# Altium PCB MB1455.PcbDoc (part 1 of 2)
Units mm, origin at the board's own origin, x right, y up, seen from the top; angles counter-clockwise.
Board outline 18.54 x 50.29 mm, 4 copper layers (Top Layer, Inner 1, Inner 2, Bottom Layer), stack 1.577 mm thick; 92 components, 84 nets, 350 pads, 195 vias.
Unrouted connection lines stored in the file: 7.
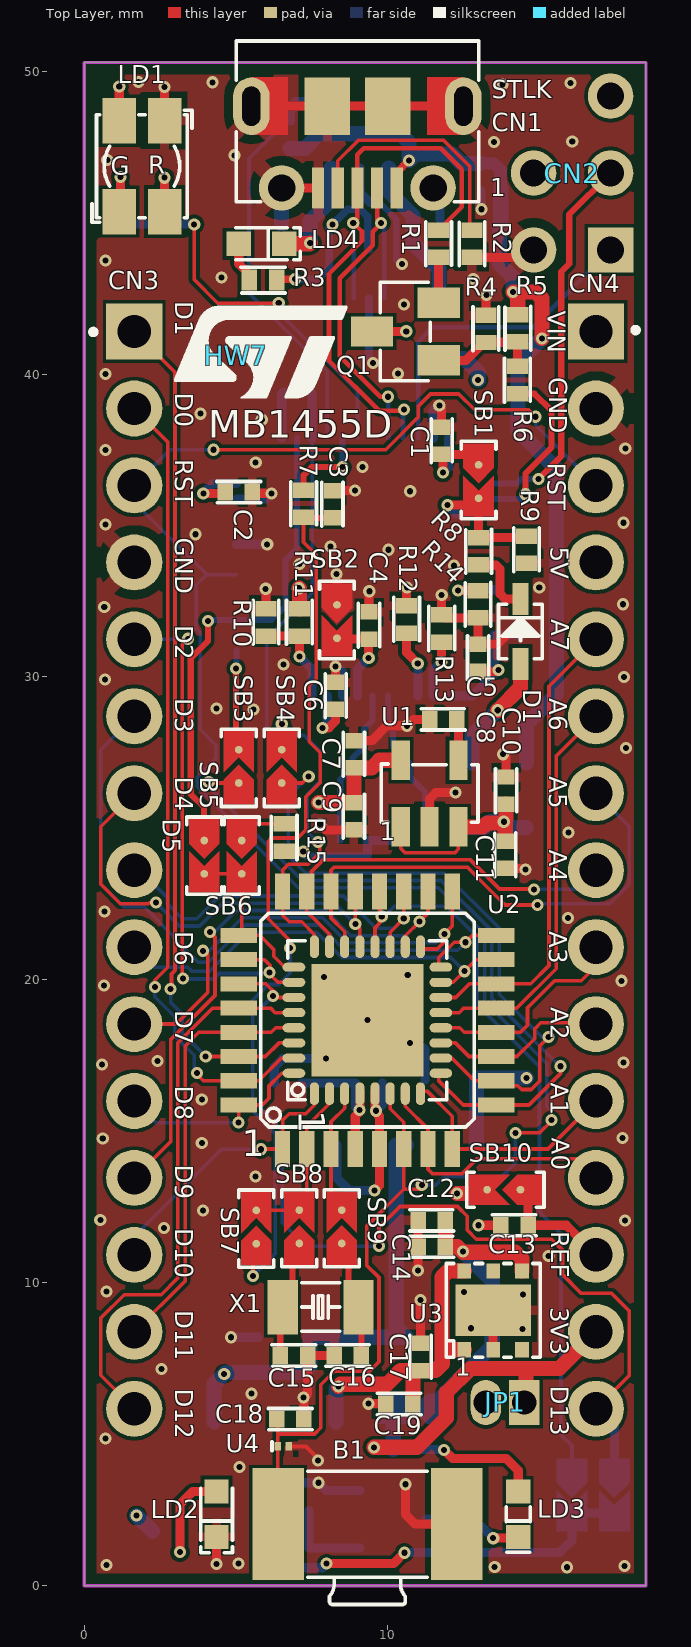
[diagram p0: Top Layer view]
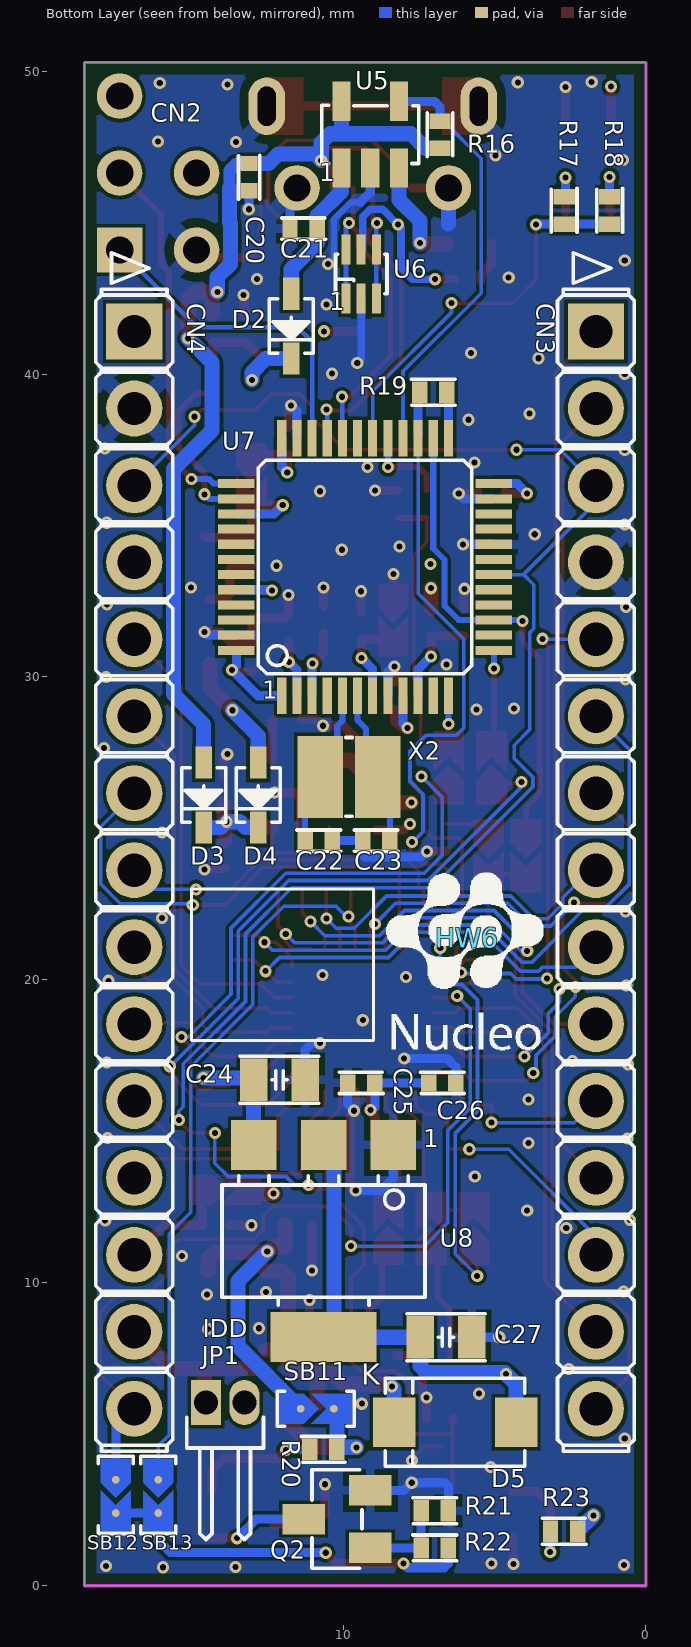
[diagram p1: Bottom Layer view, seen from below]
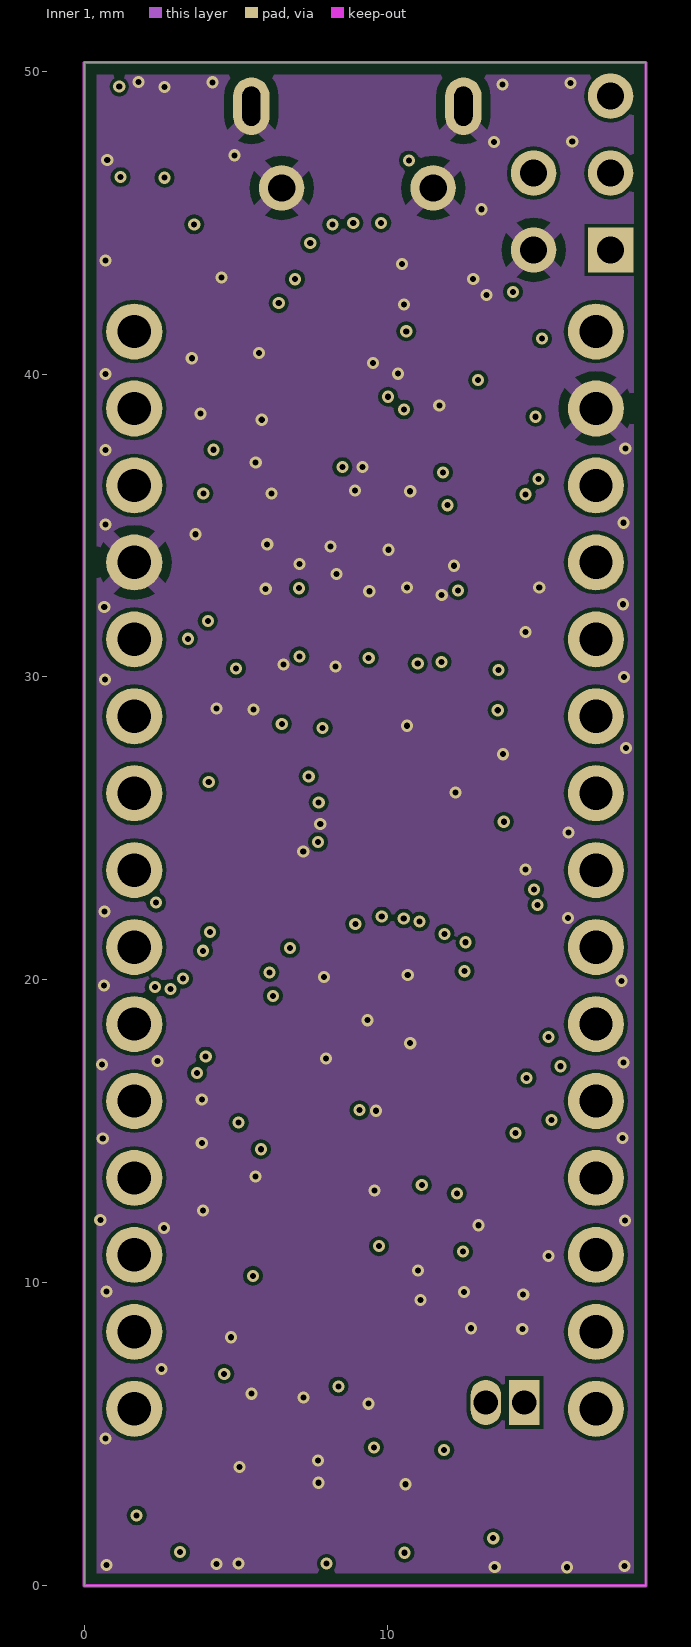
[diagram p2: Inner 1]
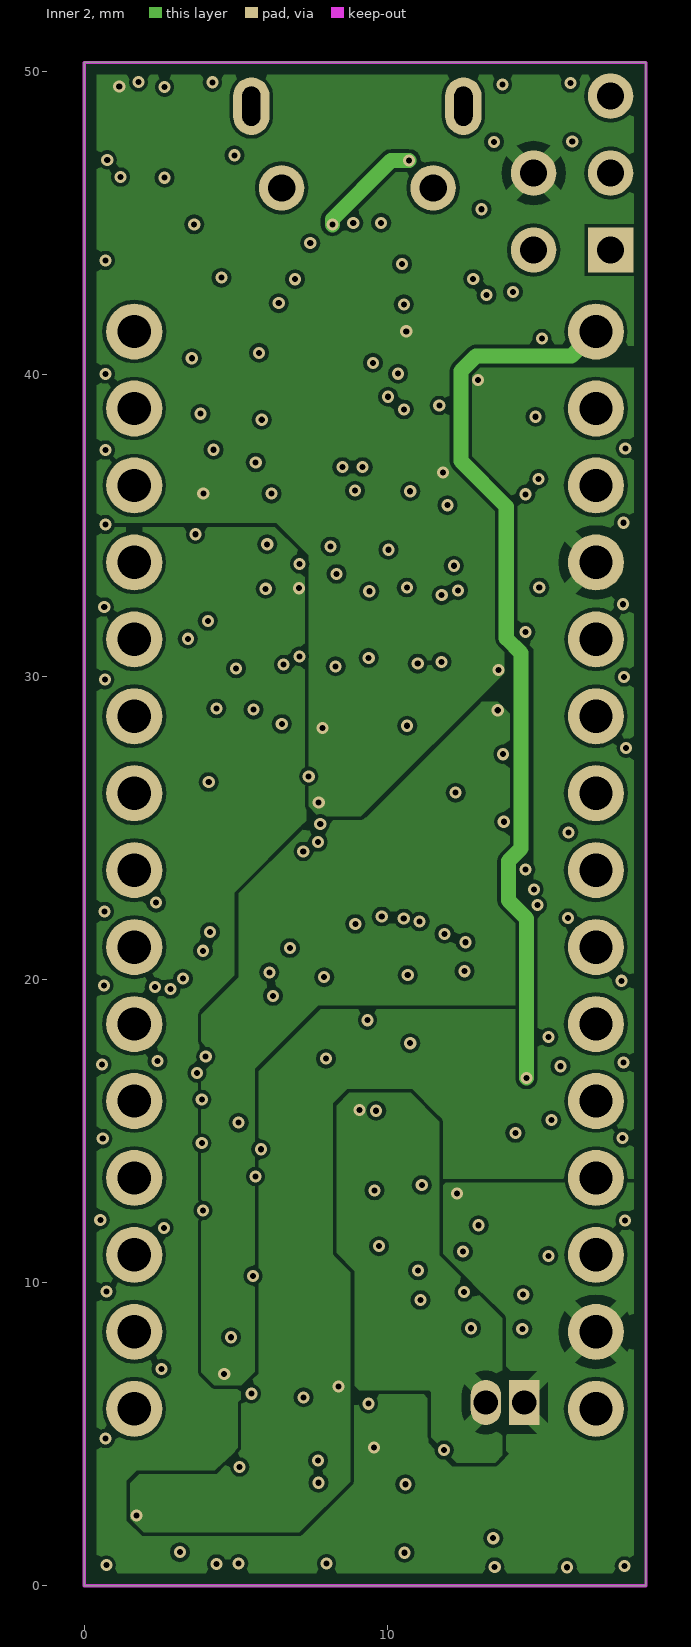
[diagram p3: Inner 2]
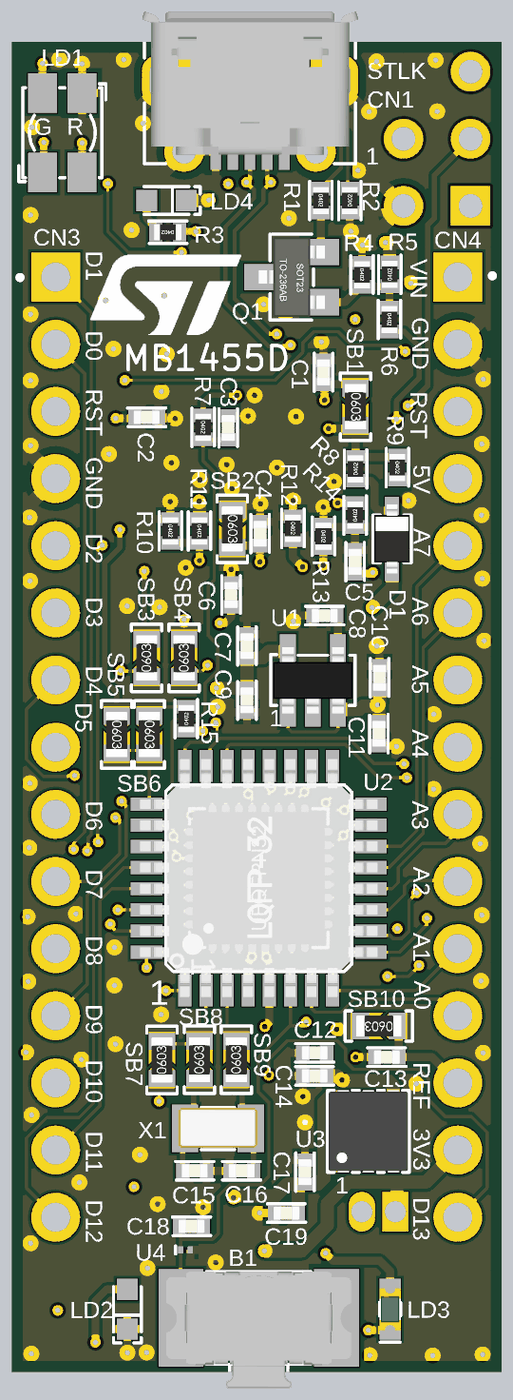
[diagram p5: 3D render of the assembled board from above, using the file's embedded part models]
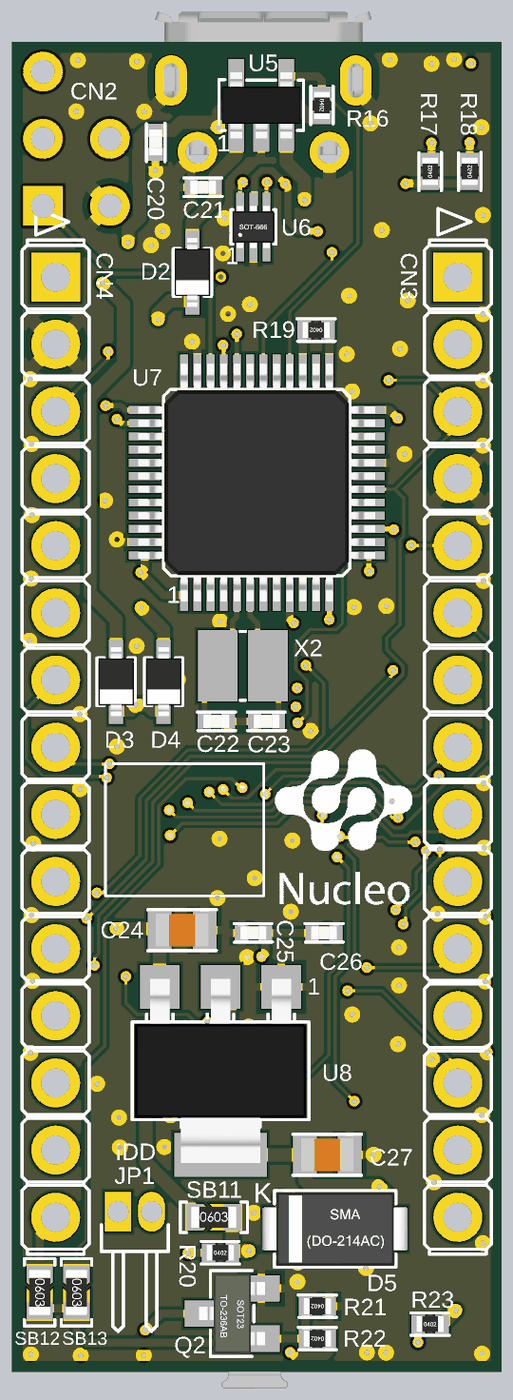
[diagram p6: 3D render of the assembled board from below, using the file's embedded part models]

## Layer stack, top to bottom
Top Solder: solder mask 0.015, Solder Resist, Dk 3.5
Top Layer: signal copper 0.035
Dielectric 1: core 0.254, FR-4, Dk 4.2
Inner 1: signal copper 0.036
Dielectric 3: prepreg 0.927, Dk 4.2
Inner 2: signal copper 0.036
Dielectric 2: core 0.254, Dk 4.2
Bottom Layer: signal copper 0.035
Bottom Solder: solder mask 0.015, Solder Resist, Dk 3.5

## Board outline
0,0 18.542,0 18.542,50.292 0,50.292

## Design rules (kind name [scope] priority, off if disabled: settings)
BoardOutlineClearance [OnLayer('Top Layer') or OnLayer('Bottom Layer') or OnLayer('Inner 1') or OnLayer('Inner 2')] p1: gap=0.4 ignorepadtopadclearanceinfootprint=FALSE
Clearance [All] p1: gap=0.12 ignorepadtopadclearanceinfootprint=FALSE
ComponentClearance [All] p1: gap=0.2 collisioncheckmode=3 verticalgap=0.2 showdistances=FALSE
DiffPairsRouting [All] p1: maxlimit=0.254 minlimit=0.2 mostfreqgap=0.254 toplayer_minwidth=0.152 toplayer_maxwidth=0.381 toplayer_prefwidth=0.381 midlayer1_minwidth=0.152 midlayer1_maxwidth=0.381 midlayer1_prefwidth=0.381 midlayer2_minwidth=0.152 midlayer2_maxwidth=0.381 midlayer2_prefwidth=0.381 bottomlayer_minwidth=0.152 bottomlayer_maxwidth=0.381 bottomlayer_prefwidth=0.381 maxuncoupledlength=25
HoleSize [All] p1: absolutevalues=TRUE maxlimit=10 minlimit=0.025 maxpercent=80.000 minpercent=20.000
MinimumSolderMaskSliver [All] p1: minsoldermaskwidth=0.1
PlaneConnect [All] p1: planeconnectstyle=Relief reliefexpansion=0.508 reliefentries=4 reliefconductorwidth=0.21 reliefairgap=0.21
PolygonConnect [All] p1: thpad.connectstyle=Relief thpad.reliefconductorwidth=0.5 thpad.reliefentries=4 thpad.polygonreliefangle="45 Angle" thpad.airgapwidth=0.3 smdpad.connectstyle=Relief smdpad.reliefconductorwidth=0.3 smdpad.reliefentries=4 smdpad.polygonreliefangle="90 Angle" smdpad.airgapwidth=0.2 via.connectstyle=Direct via.reliefconductorwidth=0.2 via.reliefentries=4 via.polygonreliefangle="90 Angle" via.airgapwidth=0.2
RoutingVias [All] p1: holewidth=0.3 width=0.8 viastyle="Through Hole" minholewidth=0.2 minwidth=0.4 maxholewidth=0.3 maxwidth=1.5
SilkToSilkClearance [All] p1: silktosilkclearance=0.1
SilkToSolderMaskClearance [IsPad] p1: minsilkscreentomaskgap=0.2 clearancetoexposedcopper=TRUE
SolderMaskExpansion SolderMaskExpansion_via [IsVia] p1: expansion=0.05 istentingtop=FALSE soldermaskfromhole=TRUE
SolderMaskExpansion [All] p2: expansion=0.102 istentingtop=FALSE
Width [All] p1: maxlimit=1 minlimit=0.12 preferedwidth=0.254 toplayer_prefwidth=0.2 midlayer1_maxwidth=0.512 midlayer2_maxwidth=0.512 bottomlayer_prefwidth=0.2 minimp=50.000000 maximp=50.000000 favimp=50.000000
23 further rules are at their usual default settings.

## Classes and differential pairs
component class Mechanical: HW3 HW6 HW7
component class U_Power: C7 C8 C9 C10 C11 C12 C14 C17 C19 C24 C27 D2 D3 D4 D5 JP1 LD2 R23 SB11 U1 U3 U8
component class U_ST_LINK_V2-1: C1 C2 C3 C4 C5 C6 C20 C21 C22 C23 CN1 CN2 D1 LD1 LD4 Q1 R1 R2 R3 R4 R5 R6 R7 R8 R9 R10 R11 R12 R13 R14 R16 R17 R18 R19 SB1 SB2 SB3 SB4 U5 U6 U7 X2
component class U_STM32G0_microcontroller: B1 C13 C15 C16 C18 C25 C26 CN3 CN4 LD3 Q2 R15 R20 R21 R22 SB5 SB6 SB7 SB8 SB9 SB10 SB12 SB13 U2 U4 X1
differential pair STLK_USB_D: +STLK_USB_D_P -STLK_USB_D_N

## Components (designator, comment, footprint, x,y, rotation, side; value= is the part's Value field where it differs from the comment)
B1 "SW-PB" SWI_C&K_ITT_KSS221G 9.347,2.032 r0 top locked value=KSS221GLFS
C1 "Capacitor" C0402 11.8,37.8 r270 top value=100nF
C2 "Capacitor" C0402 5.1,36.1 r180 top value=100nF
C3 "Capacitor" C0402 8.19,35.7 r270 top value=20pF
C4 "Capacitor" C0402 9.4,31.7 r270 top value=100nF
C5 "Capacitor" C0402 13,30.634 r270 top value=100nF
C6 "Capacitor" C0402 8.3,29.38 r270 top value=100nF
C7 "Capacitor" C0402 8.9,27.45 r270 top value=100nF
C8 "Capacitor" C0402 11.85,28.6 r0 top value=10nF
C9 "Capacitor" C0402 8.9,25.4 r90 top value=1uF
C10 "Capacitor" C0402 13.926,26.248 r270 top value=1uF
C11 "Capacitor" C0402 13.9,24.132 r90 top value=100nF
C12 "Capacitor" C0402 11.47,12.06 r0 top value=1uF
C13 "Capacitor" C0402 14.2,11.9 r0 top value=100nF
C14 "Capacitor" C0402 11.47,11.19 r0 top value=100nF
C15 "Capacitor" C0402 6.921,7.6 r180 top value=5.6pF
C16 "Capacitor" C0402 8.7,7.6 r0 top value=5.6pF
C17 "Capacitor" C0402 11.1,7.55 r270 top value=100nF
C18 "Capacitor" C0402 6.8,5.5 r180 top value=100nF
C19 "Capacitor" C0402 10.4,6 r0 top value=1uF
C20 "Capacitor" C0402 13.1,46.5 r90 bottom value=1uF
C21 "Capacitor" C0402 11.3,44.8 r180 bottom value=100nF
C22 "Capacitor" C0402 10.8,24.6 r0 bottom value=10pF
C23 "Capacitor" C0402 8.9,24.6 r180 bottom value=10pF
C24 "Capacitor" C0805 12.1,16.7 r0 bottom value=10uF
C25 "Capacitor" C0402 9.4,16.6 r180 bottom value=100nF
C26 "Capacitor" C0402 6.722,16.6 r0 bottom value=4.7uF
C27 "Capacitor" C0805 6.6,8.204 r0 bottom value=10uF
CN1 "USB_uB_105017.0001" CON_USBMICROB_MOLEX_105017-0001_H2P90 9.017,50.292 r180 top locked value=USB_uB_105017-0001
CN2 "Header STLINK" HDR_1x5_2R54_V_M 17.374,44.094 r90 top locked value=N/A
CN3 "Header 15x1" CON_LYCN_313115S161145 1.651,23.622 r270 bottom locked value="Header 15X1"
CN4 "Header 15x1" CON_LYCN_313115S161145 16.891,23.622 r270 bottom locked value="Header 15X1"
D1 "BAT60JFILM" DIO_SOD323 14.4,31.5 r90 top
D2 "BAT60JFILM" DIO_SOD323 11.71,41.58 r270 bottom
D3 "BAT60JFILM" DIO_SOD323 14.6,26.1 r270 bottom
D4 "BAT60JFILM" DIO_SOD323 12.8,26.1 r270 bottom
D5 "STPS1L40M" DIO_SMA_1A_2K 6.3,5.4 r180 bottom locked value=STPS1L30A
HW6 "Logo" LOGO_NUCLEO 5.9,21.39 r180 bottom value="LOGO NUCLEO"
HW7 "Logo" ST_LOGO_5mm 5,40.6 r0 top value=N/A
JP1 "Jumper_Header1.27 2x1 Fitted" CON_WP_707-2-02-2-20-00 13.89,6.05 r180 top value="Header 2x1"
LD1 "LD_BICOLOR_CMS" LED_BI-GR_HSMF-A201-A00J1 1.905,46.863 r180 top locked value=Red/Yellow-Green
LD2 "LED_red" LED_0603_VISHAY_VLMS1300-GS08_RED_1A2K_H0P8 4.369,2.362 r270 top locked value=Red
LD3 "LED_green" LED_0603_GREEN 14.326,2.362 r270 top locked value=Green
LD4 "LED_red" LED_0603_VISHAY_VLMS1300-GS08_RED_1A2K_H0P8 5.85,44.3 r0 top value=Red
Q1 "9013-SOT23" NPN_SOT23 10.6,41.402 r90 top value=BSR14
Q2 "9013-SOT23" NPN_SOT23 10.2,2.2 r90 bottom value=BSR14
R1 "Resistor" R0402 11.7,44.3 r270 top value=1K5
R2 "Resistor" R0402 12.8,44.3 r90 top value=100K
R3 "Resistor" R0402 5.9,43.1 r180 top value=1K
R4 "Resistor" R0402 13.26,41.49 r270 top value=36K
R5 "Resistor" R0402 14.313,41.51 r90 top value=10K
R6 "Resistor" R0402 14.3,39.8 r270 top value=100R
R7 "Resistor" R0402 7.24,35.72 r270 top value=100R
R8 "Resistor" R0402 13.017,34.15 r90 top value=2K7
R9 "Resistor" R0402 14.6,34.2 r270 top value=4K7
R10 "Resistor" R0402 6,31.8 r270 top value=4K7
R11 "Resistor" R0402 7.1,31.8 r270 top value=4K7
R12 "Resistor" R0402 10.643,31.9 r270 top value=10K
R13 "Resistor" R0402 11.8,31.6 r270 top value=10K
R14 "Resistor" R0402 13,32.4 r90 top value=100K
R15 "Resistor" R0402 6.6,24.7 r90 top value=10K
R16 "Resistor" R0402 6.8,47.9 r270 bottom value=10K
R17 "Resistor" R0402 2.7,45.4 r90 bottom value=560R
R18 "Resistor" R0402 1.2,45.4 r90 bottom value=560R
R19 "Resistor" R0402 7.021,39.4 r0 bottom value=100R
R20 "Resistor" R0402 10.65,4.5 r180 bottom value=510R
R21 "Resistor" R0402 6.971,2.475 r0 bottom value=100K
R22 "Resistor" R0402 6.971,1.25 r0 bottom value=47K
R23 "Resistor" R0402 2.7,1.8 r180 bottom value=1K
SB1 "SB_ON" SOLDER-BRIDGE_R0603-0R 13.017,36.5 r270 top value=0R
SB2 "SB_ON" SOLDER-BRIDGE_R0603-0R 8.343,31.88 r270 top value=0R
SB3 "SB_ON" SOLDER-BRIDGE_R0603-0R 5.1,27 r90 top value=0R
SB4 "SB_ON" SOLDER-BRIDGE_R0603-0R 6.521,27 r90 top value=0R
SB5 "SB_ON" SOLDER-BRIDGE_R0603-0R 3.96,24.1 r270 top value=0R
SB6 "SB_ON" SOLDER-BRIDGE_R0603-0R 5.2,24.1 r270 top value=0R
SB7 "SB_ON" SOLDER-BRIDGE_R0603-0R 5.68,11.79 r90 top value=0R
SB8 "SB_ON" SOLDER-BRIDGE_R0603-0R 7.1,11.8 r90 top value=0R
SB9 "SB_ON" SOLDER-BRIDGE_R0603-0R 8.5,11.8 r90 top value=0R
SB10 "SB_ON" SOLDER-BRIDGE_R0603-0R 13.9,13.075 r180 top value=0R
SB11 "SB_ON" SOLDER-BRIDGE_R0603-0R 10.9,5.842 r180 bottom value=0R
SB12 "SB_ON" SOLDER-BRIDGE_R0603-0R 17.5,3 r270 bottom value=0R
SB13 "SB_ON" SOLDER-BRIDGE_R0603-0R 16.1,3 r270 bottom value=0R
U1 "LDK120M33R" REG_SOT23-5L 11.4,26.15 r0 top
U2 "STM32G031K8T6U" ICC_LQFP32_7X7_P080__UFQFPN32-EPAD_5X5_P050__DI 9.347,18.669 r0 top value=STM32G031K8T6
U3 "LD39050PU33R" ICC_DFN6-EPAD_3X3_P095 13.5,9.09 r0 top
U4 "ESD-TRANSIL" ESD_0201_H0P3_1K_2A_REF2 6.571,4.602 r0 top value=ESDZL5-1F4
U5 "STMPS2141STR" MOS_SOT23-5L 9.1,47.9 r180 bottom
U6 "USBLC6-2P6" ESD_SOT666 9.4,43.3 r180 bottom
U7 "STM32F103CBT6" ICC_LQFP48_7X7_P050 9.271,33.63 r180 bottom locked
U8 "LD1117S50TR" REG_SOT223-TAB 10.643,11.379 r0 bottom
X1 "XTAL_2_PINS" CRY_NX3215SA_2P 7.8,9.2 r0 top value=32.768kHz
X2 "XTAL_2_PINS" CRY_NX3225GD_2P 9.8,26.7 r180 bottom value=8MHz

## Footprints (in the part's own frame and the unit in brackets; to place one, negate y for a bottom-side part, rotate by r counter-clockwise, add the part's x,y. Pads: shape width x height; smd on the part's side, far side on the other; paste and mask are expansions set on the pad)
C0402 [mm]
  rect 0.51x0.56 smd mask+0.05: 1(-0.45,0) 2(0.45,0)
  silkscreen extent -0.72,-0.35 0.72,0.35, body extent -0.5,-0.3 0.5,0.3, height 0.4
C0805 [mm]
  rect 0.9x1.4 smd mask+0.05: 1(-0.85,0) 2(0.85,0)
  silkscreen extent -1.3,-0.77 1.3,0.77, body extent -1.1,-0.7 1.1,0.7, height 1.35
CON_LYCN_313115S161145 [mm]
  rect 1.85x1.85 / inner round 1.85 / far side rect 1.85x1.85 hole 1.1 mask+0.05: 1(-17.78,0)
  round 1.85 hole 1.1 mask+0.05: 2(-15.24,0) 3(-12.7,0) 4(-10.16,0) 5(-7.62,0) 6(-5.08,0) 7(-2.54,0) 8(0,0) 9(2.54,0) 10(5.08,0) 11(7.62,0) 12(10.16,0) 13(12.7,0) 14(15.24,0) 15(17.78,0)
  silkscreen extent -20.38,-1.27 19.18,1.27, body extent -19.18,-1.27 19.18,1.27, height 8.5
CON_USBMICROB_MOLEX_105017-0001_H2P90 [mm]
  rect 0.4x1.35 smd mask+0.05: 1(-1.3,4.15) 2(-0.65,4.15) 3(0,4.15) 4(0.65,4.15) 5(1.3,4.15)
  round 1.5 hole 0.9 mask+0.05: 6(-2.5,4.15) 7(2.5,4.15)
  oval 1.2x1.9 hole 0.6 slot 1.3 at 90 deg mask+0.05: 8(3.5,1.45) 9(-3.5,1.45)
  rect 1.5x1.9 smd mask+0.05: 10(-1,1.45) 11(1,1.45)
  Top Layer region: 2.3,2.4 3.5,2.4 3.5,0.5 2.3,0.5
  Top Layer region: -3.5,2.4 -2.3,2.4 -2.3,0.5 -3.5,0.5
  silkscreen extent -4,-0.7 4,4.6, body extent -4.1,-1.15 4.1,4.66, height 2.9
CON_WP_707-2-02-2-20-00 [mm]
  rect 1x1.5 hole 0.8 mask+0.05: 1(-0.635,0)
  oval 1x1.5 hole 0.8 mask+0.05: 2(0.635,0)
CRY_NX3215SA_2P [mm]
  rect 1x1.8 smd mask+0.05: 1(-1.25,0) 2(1.25,0)
  silkscreen extent -0.63,-0.8 0.63,0.8, body extent -1.65,-0.8 1.65,0.8, height 0.9
CRY_NX3225GD_2P [mm]
  rect 1.5x2.7 smd mask+0.05: 1(-0.95,0) 2(0.95,0)
  silkscreen extent -0.1,-1.3 0.1,1.3, body extent -1.65,-1.3 1.65,1.3, height 1
DIO_SMA_1A_2K [mm]
  rect 1.4x1.64 smd mask+0.05: 1(2.015,0) 2(-2.015,0)
  silkscreen extent -2.3,-1.45 2.3,1.45, body extent -2.75,-1.45 2.75,1.45, height 2.7
DIO_SOD323 [mm]
  rect 1.06x0.54 smd mask+0.05: 1(-1.07,0) 2(1.07,0)
  silkscreen extent -0.9,-0.72 0.9,0.72, body extent -1.3,-0.78 1.3,0.78, height 1.17
ESD_0201_H0P3_1K_2A_REF2 [mm] "MCD-03501"
  rect 0.212x0.275 smd paste+0 mask-0.025: 1(-0.181,0) 2(0.181,0)
  silkscreen extent -0.38,-0.15 -0.38,0.15, body extent -0.3,-0.17 0.3,0.17, height 0.3
ESD_SOT666 [mm]
  rect 0.3x0.99 smd mask+0.05: 1(-0.5,-0.805) 2(0,-0.805) 3(0.5,-0.805) 4(0.5,0.805) 5(0,0.805) 6(-0.5,0.805)
  silkscreen extent -0.85,-0.65 0.85,0.65, body extent -0.85,-0.8 0.85,0.8, height 0.6
HDR_1x5_2R54_V_M [mm] "Header IDC, 2 x 4 Pin Vertical 2.54mm Pitch (Non-Boxed, Male)"
  rect 1.5x1.5 hole 0.9: 1(0,0)
  round 1.5 hole 0.9: 2(0,2.54) 3(2.54,0) 4(2.54,2.54) 5(5.08,0)
ICC_DFN6-EPAD_3X3_P095 [mm]
  rect 0.45x0.5 smd mask+0.05: 1(-0.95,-1.3) 2(0,-1.3) 3(0.95,-1.3) 4(0.95,1.3) 5(0,1.3) 6(-0.95,1.3)
  rect 2.5x1.7 smd mask+0.05: EP(0,0)
  silkscreen extent -1.55,-1.55 1.55,1.55, body extent -1.55,-1.55 1.55,1.55, height 1
ICC_LQFP32_7X7_P080__UFQFPN32-EPAD_5X5_P050__DI [mm] "MCD-01396"
  rect 0.5x1.2 smd mask+0.05: 1(-2.8,-4.25) 2(-2,-4.25) 3(-1.2,-4.25) 4(-0.4,-4.25) 5(0.4,-4.25) 6(1.2,-4.25) 7(2,-4.25) 8(2.8,-4.25) 17(2.8,4.25) 18(2,4.25) 19(1.2,4.25) 20(0.4,4.25) 21(-0.4,4.25) 22(-1.2,4.25) 23(-2,4.25) 24(-2.8,4.25)
  oval 0.3x0.75 smd mask+0.05: 1(-1.75,-2.425) 2(-1.25,-2.425) 3(-0.75,-2.425) 4(-0.25,-2.425) 5(0.25,-2.425) 6(0.75,-2.425) 7(1.25,-2.425) 8(1.75,-2.425) 17(1.75,2.425) 18(1.25,2.425) 19(0.75,2.425) 20(0.25,2.425) 21(-0.25,2.425) 22(-0.75,2.425) 23(-1.25,2.425) 24(-1.75,2.425)
  oval 0.75x0.3 smd mask+0.05: 9(2.425,-1.75) 10(2.425,-1.25) 11(2.425,-0.75) 12(2.425,-0.25) 13(2.425,0.25) 14(2.425,0.75) 15(2.425,1.25) 16(2.425,1.75) 25(-2.425,1.75) 26(-2.425,1.25) 27(-2.425,0.75) 28(-2.425,0.25) 29(-2.425,-0.25) 30(-2.425,-0.75) 31(-2.425,-1.25) 32(-2.425,-1.75)
  rect 1.2x0.5 smd mask+0.05: 9(4.25,-2.8) 10(4.25,-2) 11(4.25,-1.2) 12(4.25,-0.4) 13(4.25,0.4) 14(4.25,1.2) 15(4.25,2) 16(4.25,2.8) 25(-4.25,2.8) 26(-4.25,2) 27(-4.25,1.2) 28(-4.25,0.4) 29(-4.25,-0.4) 30(-4.25,-1.2) 31(-4.25,-2) 32(-4.25,-2.8)
  rect 3.7x3.7 smd mask+0.05: 33(0,0)
  silkscreen extent -3.52,-3.52 3.52,3.52, body extent -4.5,-4.5 4.5,4.5, height 1.63
ICC_LQFP48_7X7_P050 [mm]
  rect 0.3x1.2 smd mask+0.05: 1(-2.75,-4.25) 2(-2.25,-4.25) 3(-1.75,-4.25) 4(-1.25,-4.25) 5(-0.75,-4.25) 6(-0.25,-4.25) 7(0.25,-4.25) 8(0.75,-4.25) 9(1.25,-4.25) 10(1.75,-4.25) 11(2.25,-4.25) 12(2.75,-4.25) 25(2.75,4.25) 26(2.25,4.25) 27(1.75,4.25) 28(1.25,4.25) 29(0.75,4.25) 30(0.25,4.25) 31(-0.25,4.25) 32(-0.75,4.25) 33(-1.25,4.25) 34(-1.75,4.25) 35(-2.25,4.25) 36(-2.75,4.25)
  rect 1.2x0.3 smd mask+0.05: 13(4.25,-2.75) 14(4.25,-2.25) 15(4.25,-1.75) 16(4.25,-1.25) 17(4.25,-0.75) 18(4.25,-0.25) 19(4.25,0.25) 20(4.25,0.75) 21(4.25,1.25) 22(4.25,1.75) 23(4.25,2.25) 24(4.25,2.75) 37(-4.25,2.75) 38(-4.25,2.25) 39(-4.25,1.75) 40(-4.25,1.25) 41(-4.25,0.75) 42(-4.25,0.25) 43(-4.25,-0.25) 44(-4.25,-0.75) 45(-4.25,-1.25) 46(-4.25,-1.75) 47(-4.25,-2.25) 48(-4.25,-2.75)
  silkscreen extent -3.52,-3.52 3.52,3.52, body extent -4.5,-4.5 4.5,4.5, height 1.6
LED_0603_GREEN [mm]
  rect 0.8x0.8 smd mask+0.05: 1(-0.75,0) 2(0.75,0)
  silkscreen extent -0.25,-0.4 1.25,0.4, body extent -0.8,-0.4 0.8,0.4, height 0.6
LED_0603_VISHAY_VLMS1300-GS08_RED_1A2K_H0P8 [mm]
  rect 0.8x0.8 smd mask+0.05: 1(-0.75,0) 2(0.75,0)
  silkscreen extent -0.85,-0.53 1.28,0.53, body extent -0.85,-0.45 0.85,0.45, height 0.8
LED_BI-GR_HSMF-A201-A00J1 [mm]
  rect 1.1x1.5 smd mask+0.05: 1(-0.75,-1.5) 2(-0.75,1.5) 3(0.75,1.5) 4(0.75,-1.5)
  silkscreen extent -1.65,-1.85 1.65,1.85, body extent -1.5,-1.85 1.5,1.85, height 2.1
LOGO_NUCLEO [mm]
  silkscreen extent -2.67,-3.71 2.51,2.13
MOS_SOT23-5L [mm]
  rect 0.6x1.3 smd mask+0.05: 1(-0.95,-1.1) 2(0,-1.1) 3(0.95,-1.1) 4(0.95,1.1) 5(-0.95,1.1)
  silkscreen extent -1.6,-0.95 1.6,0.97, body extent -1.52,-1.25 1.52,1.25, height 1.45
NPN_SOT23 [mm]
  rect 1x1.4 smd mask+0.05: 1(-0.95,-1.1) 2(0.95,-1.1) 3(0,1.1)
  silkscreen extent -1.63,-0.82 1.63,0.82, body extent -1.56,-1.25 1.56,1.25, height 1.1
R0402 [mm]
  rect 0.51x0.7 smd mask+0.05: 1(-0.45,0) 2(0.45,0)
  silkscreen extent -0.72,-0.43 0.72,0.43, body extent -0.52,-0.3 0.52,0.3, height 0.4
REG_SOT23-5L [mm]
  rect 0.6x1.3 smd mask+0.05: 1(-0.95,-1.1) 2(0,-1.1) 3(0.95,-1.1) 4(0.95,1.1) 5(-0.95,1.1)
  silkscreen extent -1.6,-0.95 1.6,0.97, body extent -1.52,-1.25 1.52,1.25, height 1.1
REG_SOT223-TAB [mm]
  rect 1.5x1.65 smd mask+0.05: 1(-2.3,-3.175) 2(0,-3.175) 3(2.3,-3.175)
  rect 3.5x1.65 smd mask+0.05: 4(0,3.175)
  silkscreen extent -3.35,-2.15 3.35,2.12, body extent -3.35,-3.48 3.35,3.48, height 1.8
SOLDER-BRIDGE_R0603-0R [mil]
  round 10 smd paste-393.7 mask+4: 1(-19.68,0) 2(23.62,0)
  Top Layer region: -5.91,19.68 13.78,0 -5.91,-19.69 47.24,-19.69 47.24,19.68
  Top Layer region: -47.24,-19.69 -47.24,19.68 -15.75,19.68 3.94,0 -15.75,-19.69
  silkscreen extent -50,-23 50,23, body extent -36,-20 36,20, height 22
ST_LOGO_5mm [mm]
  silkscreen extent -2.03,-1.39 3.68,1.65
SWI_C&K_ITT_KSS221G [mm] "MCD-01335"
  rect 1.7x3.7 smd mask+0.05: 1(-2.95,0) 2(2.95,0)
  silkscreen extent -1.97,-2.65 1.97,1.75, body extent -3.5,-2.65 3.5,1.76, height 1.7

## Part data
B1: library part MCD-01335, "Subminiature Side Actuated Tact Switch for SMT - KSS series - 2.0 Newtons - Gull wing, SPST", Manufacturer=C&K, Manufacturer_HQ_COO=Unknown, Manufacturer_Part_Number=KSS221GLFS, Package=4.2x7mm
C1 C2 C4 C5 C6 C7 C11 C13 C14 C17 C18 C21 C25: library part MCD-00006, "Capacitor, MLCC, 100nF, 16V, X7R, +/-10%, 0402, T=0.5mm", Manufacturer=YAGEO, Manufacturer_Part_Number=CC0402KRX7R7BB104, Package=0402
C3: library part MCD-00016, "Capacitor, MLCC, 20pF, 50V, NPO, 5%, 0402, T=0,5mm", Manufacturer=YAGEO, Manufacturer_Part_Number=CC0402JRNPO9BN200, Package=0402
C8: library part MCD-00011, "Capacitor, MLCC, 10nF, 16V, X7R, 10%, 0402, T=0.5mm", Manufacturer=YAGEO, Manufacturer_Part_Number=CC0402KRX7R7BB103, Package=0402
C9 C10 C12 C19 C20: library part MCD-00095, "Capacitor, MLCC, 1uF, 6V3, X5R, 10%, 0402, T=0,5mm", Alternate_Manufacturer=MURATA, Alternate_Manufacturer_Part_Number=GRM155R60J105KE19, Manufacturer_Part_Number=GRM155R61E105KA12, Package=0402
C15 C16: library part MCD-01374, "Capacitor, MLCC, 5.6pF, 50V, NPO, +/- 0.1pF, 0402, T=0,5mm", Manufacturer=YAGEO, Manufacturer_Part_Number=CC0402BRNPO9BN5R6, Package=0402
C22 C23: library part MCD-00015, "Capacitor, MLCC, 10pF, 50V, NPO, 5%, 0402, T=0,5mm", Manufacturer=YAGEO, Manufacturer_Part_Number=CC0402JRNPO9BN100, Package=0402
C24 C27: library part MCD-00014, "Capacitor, MLCC, 10uF, 25V, X5R, 10%, 0805, T=0,85mm", Manufacturer=YAGEO, Manufacturer_Part_Number=CC0805KRX5R8BB106, Package=0805
C26: library part MCD-01356, "Capacitor, MLCC, 4.7uF, 6V3, X5R, 20%, 0402, T=0.5mm", Manufacturer=MURATA, Manufacturer_Part_Number=GRM155R60J475ME47, Package=0402
CN1: library part MCD-00028, "USB-MICRO-B, 0.65mm, RA, SMT, Bottom Mount,", Manufacturer=MOLEX, Manufacturer_Part_Number=1050170001
CN2: library part MCD-01399, "Header 5 pads for ST-LINK prog. Not fitted", Manufacturer=n/a, Manufacturer_HQ_COO=Unknown
CN3 CN4: library part MCD-01332, "Pin header, 15x1, 2,54mm, VR, TH, Height 6mm/6mm", Alternate_Manufacturer=SAMTEC, Alternate_Manufacturer_Part_Number="TSW 115-08-F-S", Manufacturer=LYCONN, Manufacturer_Part_Number=313115S161145
D1 D2 D3 D4: library part MCD-00034, Manufacturer=STMICROELECTRONICS, Manufacturer_HQ_COO=EU, Package=SOD-323
D5: library part MCD-01059, "LOW DROP POWER SCHOTTKY RECTIFIER 1A 30V VF=0.3V", Manufacturer=STMICROELECTRONICS, Manufacturer_HQ_COO=EU, Manufacturer_Part_Number=STPS1L30A, Package=SMA
HW6: library part MCD-00636, "NUCLEO logo footprint for PCB", Manufacturer=N/A, Manufacturer_HQ_COO=Unknown
HW7: library part MCD-00625, "STMicroelectronics logo footprint for PCB", Manufacturer=n/a, Manufacturer_HQ_COO=Unknown
JP1: library part MCD-01428, "Header, 2x1, 1,27mm, Right Angled, Single Row, Height 3.05mm/1.27mm", Manufacturer="W&P PRODUCTS", Manufacturer_Part_Number=707-2-02-2-20-00
LD1: library part MCD-02402, "LED Bicolor, Red/Yellow-Green , 2V, 20mA, 4-PLCC", Manufacturer=EVERLIGHT, Manufacturer_Part_Number=67-22SURSYGC/S530-A2/TR8, Package=4-PLCC
LD2 LD4: library part MCD-02787, "LED, Red, 1V7 to 2V2, 5mA, 0603", Manufacturer=EVERLIGHT, Manufacturer_Part_Number=19-217/R6C-AL1M2VY/6T, Package=0603
LD3: library part MCD-02900, "LED, Green, 2V, 20mA, 0603", Manufacturer=EVERLIGHT, Manufacturer_Part_Number=19-213SYGC/S530-E2/5T, Package=0603
Q1 Q2: library part MCD-00073, "NPN Bipolar Transistor", Alternate_Manufacturer="ON SEMICONDUCTOR", Alternate_Manufacturer_Part_Number="MMBT2222LT1G / MMBT2222ALT1G / MMBT2222ALT3G", Manufacturer_Part_Number=BSR14, Package=SOT-23
R1: library part MCD-00068, "Resistor,1K5,0402,1%,1/16W", Manufacturer=YAGEO, Manufacturer_Part_Number=RC0402FR-071K5L, Package=0402
R2 R14 R21: library part MCD-00059, "Resistor,100K,0402,1%,1/16W", Alternate_Manufacturer=YAGEO, Alternate_Manufacturer_Part_Number=RT0402FRE07100KL, Manufacturer_Part_Number=RC0402FR-07100KL, Package=0402
R3 R23: library part MCD-00061, "Resistor,1K,0402,1%,1/16W", Manufacturer=YAGEO, Manufacturer_Part_Number=RC0402FR-071KL, Package=0402
R4: library part MCD-00069, "Resistor,36K,0402,1%,1/16W", Manufacturer=YAGEO, Manufacturer_Part_Number=RC0402FR-0736KL, Package=0402
R5 R12 R13 R15 R16: library part MCD-00053, "Resistor,10K,0402,1%,1/16W", Manufacturer=YAGEO, Manufacturer_Part_Number=RC0402FR-0710KL, Package=0402
R6 R7 R19: library part MCD-00067, "Resistor,100R,0402,1%,1/16W", Manufacturer=YAGEO, Manufacturer_Part_Number=RC0402FR-07100RL, Package=0402
R8: library part MCD-00055, "Resistor,2K7,0402,1%,1/16W", Manufacturer=YAGEO, Manufacturer_Part_Number=RC0402FR-072K7L, Package=0402
R9 R10 R11: library part MCD-00065, "Resistor,4K7,0402,1%,1/16W", Alternate_Manufacturer=YAGEO, Alternate_Manufacturer_Part_Number=RT0402FRE074K7L, Manufacturer_Part_Number=RC0402FR-074K7L, Package=0402
R17 R18: library part MCD-00489, "Resistor, 560R, 0402, +/-1%, 1/16W", Manufacturer=YAGEO, Manufacturer_Part_Number=RC0402FR-07560RL, Package=0402
R20: library part MCD-00064, "Resistor,510R,0402,1%,1/16W", Manufacturer=YAGEO, Manufacturer_Part_Number=RC0402FR-07510RL, Package=0402
R22: library part MCD-00063, "Resistor,47K,0402,1%,1/16W", Manufacturer=YAGEO, Manufacturer_Part_Number=RC0402FR-0747KL, Package=0402
SB1 SB2 SB6 SB7 SB12: library part MCD-00071, "Resistor, 0R, SB0603, 5%, 0.1W", Manufacturer=YAGEO, Manufacturer_HQ_COO=Unknown, Manufacturer_Part_Number=RC0603JR-070RL, Package=0603
SB3 SB4 SB5 SB8 SB9 SB10 SB11 SB13: library part MCD-00071, "Solder Bridge ON", Manufacturer=YAGEO, Manufacturer_HQ_COO=Unknown, Manufacturer_Part_Number=RC0603JR-070RL, Package=0603
U1: library part MCD-00663, "200 mA low quiescent current very low noise LDO", Manufacturer=STMICROELECTRONICS, Manufacturer_HQ_COO=EU, Package=SOT23-5
U2: library part MCD-01738, "MCU, ARM Cortex-M0+ 32-bit, 64KB Flash, 8KB RAM, With Crypto", Manufacturer=STMICROELECTRONICS, Manufacturer_HQ_COO=EU, Manufacturer_Part_Number=STM32G031K8T6, Package=LQFP32
U3: library part MCD-00215, "Low quiescent current and low noise voltage regulators", Manufacturer=STMICROELECTRONICS, Package=DFN-6
U4: library part MCD-03501, "Diode, ESD TVS, 5V5, 100nA, 10V, 0201", Manufacturer=STMICROELECTRONICS, Manufacturer_Part_Number=ESDZL5-1F4, Package=0201
U5: library part MCD-00083, "Enhanced single channel power switches with active low enable pin", Alternate_Manufacturer="TEXAS INSTRUMENTS", Alternate_Manufacturer_Part_Number=TPS2041C, Manufacturer=STMICROELECTRONICS, Manufacturer_HQ_COO=EU, Package=SOT23-5
U6: library part MCD-00169, "USB OTG FS ESD protection", Manufacturer=STMICROELECTRONICS, Package=SOT666-6
U7: library part MCD-00085, "Medium-density performance line ARM-based 32-bit MCU with 128KB Flash", Manufacturer=STMICROELECTRONICS, Manufacturer_HQ_COO=EU, Package=LQFP48
U8: library part MCD-00088, "IC REG LDO 5V 0.8A SOT223", Manufacturer=STMICROELECTRONICS, Manufacturer_HQ_COO=EU, Package=SOT223-4
X1: library part MCD-00091, "Crystal 32.768kHz, 6pF, +-20ppm, 50Kohms max, SMD", Manufacturer=NDK, Manufacturer_Part_Number=NX3215SA-32.768KHz-EXS00A-MU00525, Package=3.2x1.5mm
X2: library part MCD-00092, "Crystal 8MHz, 8pF, +-20ppm, 500ohms max,  SMD", Manufacturer=NDK, Manufacturer_Part_Number=NX3225GD-8MHz-EXS00A-CG04874, Package=3.2x2.5mm

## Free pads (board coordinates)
  round 0.508 on Mech16: 1(-11.115,-24.702) 1(37.732,-24.702)

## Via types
v1: diameter 0.4, hole 0.2, Top Layer to Bottom Layer, 195 vias

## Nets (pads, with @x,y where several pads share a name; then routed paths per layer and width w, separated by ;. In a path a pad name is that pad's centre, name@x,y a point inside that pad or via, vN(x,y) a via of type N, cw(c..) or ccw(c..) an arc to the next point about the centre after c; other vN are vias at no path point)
3V3: CN4.14 JP1.1 R11.1 R20.2 SB10.2 SB11.2 | length 14.5
  Top Layer w0.5: v1(7.09,32.93) 7.1,32.92 R11.1@7.1,32.25 ; v1(9.56,4.57) 10.98,4.57 11.95,5.54 11.95,6.37 12.75,7.17 15.679,7.17 CN4.14@16.891,8.382 ; v1(12.3,12.95) 13.3,12.95 SB10.2@13.3,13.075 ; JP1.1@14.53,5.809 14.53,6.14 14.58,6.19 14.58,7.02
  Bottom Layer w0.5: v1(9.56,4.57) 10.13,4.57 R20.2@10.2,4.5 10.2,5.742 SB11.2@10.3,5.842
3V3_STLK: C1.2 C2.2 C5.2 C6.2 C7.2 C9.2 CN2.4 LD1.4 Q1.3 SB1.1 U1.5 U7.1 U7.9 U7.24 U7.36 U7.48 | length 16.9
  Top Layer w0.3: LD1.4@1.155,48.363 v1(1.155,49.485) ; v1(3.93,36.06) 4.61,36.06 C2.2@4.65,36.1 ; v1(7.87,28.32) 8.07,28.32 8.3,28.55 C6.2@8.3,28.93 ; Q1.3@9.5,41.402 9.508,41.41 v1(10.63,41.41) ; v1(11.84,36.75) 11.84,37.31 C1.2@11.8,37.35 12.78,37.35 13.017,37.113 SB1.1@13.017,37 ; C5.2@13,30.184 13.624,30.184 v1(13.67,30.23)
  Top Layer w0.5: v1(7.74,25.86) 7.75,25.85 C9.2@8.9,25.85 C7.2@8.9,27 9.49,27 9.74,27.25 U1.5@10.45,27.25
  Bottom Layer w0.3: v1(3.93,36.06) 4.25,36.38 U7.24@5.021,36.38 ; v1(7.87,28.32) v1(7.87,28.32) 8.021,28.469 U7.9@8.021,29.38 ; v1(11.84,36.75) 12.021,36.931 U7.36@12.021,37.88 ; U7.1@12.021,29.38 12.807,29.38 13.658,30.23 v1(13.67,30.23) 13.521,30.379 U7.48@13.521,30.88
5V: C17.2 C19.2 CN4.4 D2.2 D5.2 R23.2 U3.1 U3.6 | length 13.2
  Top Layer w0.5: v1(8.39,6.58) 8.46,6.65 9.99,6.65 10.44,7.1 C17.2@11.1,7.1 11.59,7.1 11.81,7.32 ; C19.2@10.85,6 C17.2@10.85,6.85 ; U3.1@12.55,7.79 11.82,7.79 11.82,7.33 11.81,7.32 ; U3.6@12.55,10.39 12.01,10.39 11.81,10.19 11.81,7.32
  Bottom Layer w0.5: v1(1.73,2.32) R23.2@2.25,1.8 ; D5.2@8.315,5.4 8.315,6.505 v1(8.39,6.58) ; D2.2@11.71,40.51 12.55,40.51 13.01,40.05 13.01,39.8 v1(13.004,39.8)
5V_USB_CHGR: C20.2 CN1.1 D3.1 R3.1 R5.2 R16.2 U5.5 U6.5 | length 42.3
  Top Layer w0.25: R3.1@6.29,43.1 6.32,43.13 v1(6.96,43.13) ; CN1.1@10.317,46.142 10.317,46.647 v1(10.72,47.05)
  Top Layer w0.5: v1(14.15,42.71) 14.89,42.71 15.11,42.49 v1(15.11,41.17) ; v1@14.25,42.67 14.313,42.607 R5.2@14.313,41.96
  Inner 2 w0.5: v1(8.19,44.93) 8.19,45.11 10.13,47.05 v1(10.72,47.05)
  Bottom Layer w0.25: v1@6.91,43.13 v1(6.96,43.13) 7.71,43.13 8.085,43.505 8.085,44.825 v1(8.19,44.93) 8.696,45.435 9.105,45.435 9.355,45.185 9.355,44.15 U6.5@9.4,44.105
  Bottom Layer w0.4: C20.2@13.1,46.95 13.52,46.95 13.75,46.72 13.75,46.134
  Bottom Layer w0.5: R16.2@6.8,47.45 7.28,47.45 7.76,47.93 10.43,47.93 10.72,47.64 v1(10.72,47.05) 10.932,47.262 12.138,47.262 12.45,46.95 C20.2@13.1,46.95 ; 10.05,48.1 U5.5@10.05,49 ; 13.75,46.134 13.75,45.01 13.714,44.974 13.714,43.63 14.15,43.194 v1(14.15,42.71) ; D3.1@14.6,27.17 14.6,28.44 15.59,29.43 15.59,36.869 14.32,38.139 14.32,40.38 v1(15.11,41.17)
5V_USB_STLK: C21.2 D2.1 U5.1 | length 4.8
  Bottom Layer w0.5: U5.1@10.05,46.8 10.05,46.025 10.85,45.225 C21.2@10.85,44.8 10.85,44.33 11.71,43.47 D2.1@11.71,42.65
AIN_1: R10.2 R11.2 U7.10 | length 3.2
  Top Layer w0.3: R10.2@6,31.35 R11.2@7.1,31.35 v1(7.1,30.68)
  Bottom Layer w0.3: v1(7.1,30.68) 7.521,30.259 U7.10@7.521,29.38
AVDD: C13.2 CN4.13 SB10.1 | length 4.2
  Top Layer w0.3: SB10.1@14.4,13.075 14.575,13.075 14.65,13.15 C13.2@14.65,11.9 15.913,11.9 CN4.13@16.891,10.922
E5V: C27.2 D1.1 D4.1 D5.1 U8.2 U8.4 | length 19.6
  Top Layer w0.5: v1(13.65,28.9) 14.4,29.65 D1.1@14.4,30.43
  Bottom Layer w0.5: D5.1@4.285,5.4 4.285,6.66 v1(4.62,6.995) 4.66,7.035 7.235,7.035 7.45,7.25 C27.2@7.45,8.204 U8.4@10.643,8.204 10.3,8.547 10.3,14.554 U8.2@10.643,14.554 ; D4.1@12.8,27.17 12.8,28.05 v1(13.65,28.9)
GND: B1.2 C1.1 C2.1 C3.1 C4.1 C5.1 C6.1 C7.1 C8.1 C9.1 C10.1 C11.1 C12.1 C13.1 C14.1 C15.1 C16.1 C17.1 C18.1 C19.1 C20.1 C21.1 C22.1 C23.1 C24.1 C25.1 C26.1 C27.1 CN1.5 CN1.6 CN1.7 CN1.8 CN1.9 CN1.10 CN1.11 CN2.2 CN3.4 CN4.2 LD1.1 LD2.2 Q2.2 R2.1 R4.1 R9.2 R10.1 R12.1 R13.1 R14.1 R15.1 R21.1 SB2.1 U1.2 U2.5 U2.33 U3.2 U3.EP U4.2 U5.2 U6.2 U7.8 U7.20 U7.23 U7.35 U7.47 U8.1 | length 77.2
  Top Layer w0.127: U4.2@6.752,4.6 7.32,4.6 7.717,4.203 v1(7.717,4.13)
  Top Layer w0.3: v1(2.65,49.47) 2.655,49.465 LD1.1@2.655,48.363 ; v1(4.369,0.72) LD2.2@4.369,1.612 ; C2.1@5.55,36.1 5.6,36.05 v1(6.18,36.05) ; v1(5.99,32.91) 6,32.91 R10.1@6,32.25 ; 6.162,48.842 CN1.11@8.017,48.842 CN1.10@10.017,48.842 CN1.9@12.517,48.842 ; CN1.7@6.517,46.142 CN1.5@7.717,46.142 ; R15.1@6.6,24.25 6.61,24.24 v1(7.23,24.24) ; C18.1@7.25,5.5 7.25,6.21 7.371,6.331 C15.1@7.371,7.6 C16.1@8.25,7.6 ; v1(7.79,25.15) 7.99,24.95 C9.1@8.9,24.95 ; C3.1@8.19,36.15 v1(8.94,36.15) ; C6.1@8.3,29.83 8.3,30.38 v1(8.3,30.35) ; v1(8.33,33.4) 8.343,33.387 SB2.1@8.343,32.38 ; C7.1@8.9,27.9 9.5,27.9 9.99,28.39 v1(10.66,28.39) 10.87,28.6 C8.1@11.4,28.6 ; v1(9.38,6.01) 9.94,6.01 C19.1@9.95,6 ; C4.1@9.4,32.15 9.4,32.82 v1(9.41,32.83) ; v1(9.58,13.05) 9.747,13.217 U2.5@9.747,14.419 9.747,15.491 9.597,15.641 U2.5@9.597,16.319 ; v1(10.6,3.35) 10.6,2.36 10.928,2.032 B1.2@12.297,2.032 ; R12.1@10.643,32.35 10.643,32.943 v1(10.65,32.95) ; v1(11.02,10.41) C12.1@11.02,11.93 ; C17.1@11.1,8 v1(11.1,9.43) ; U1.2@11.4,25.05 11.4,25.98 11.6,26.18 v1(12.26,26.18) ; v1(11.72,38.96) 11.8,38.88 C1.1@11.8,38.25 ; v1(11.8,32.7) R13.1@11.8,32.05 11.9,31.95 R14.1@13,31.95 C5.1@13,31.084 13.634,31.084 14.03,31.48 v1(14.57,31.48) ; R2.1@12.8,43.85 14.589,43.85 CN2.2@14.834,44.094 ; v1(13.02,11.9) C13.1@13.75,11.9 ; R4.1@13.26,41.94 13.26,42.59 v1(13.28,42.61) ; U3.2@13.5,7.79 U3.EP@13.5,9.09 ; v1(13.82,27.45) 13.85,27.45 13.926,27.374 C10.1@13.926,26.698 ; C11.1@13.9,23.682 14.538,23.682 v1(14.57,23.65)
  Bottom Layer w0.2: 9.429,45.67 9.74,45.67 10.3,45.11 10.3,43.77 10.44,43.63 v1(10.49,43.63)
  Bottom Layer w0.25: U6.2@9.4,42.495 9.4,40.5 v1(9.53,40.37)
  Bottom Layer w0.3: v1(4.844,8.204) C27.1@5.75,8.204 ; U7.20@5.021,34.38 v1(6.04,34.38) ; U7.23@5.021,35.88 6.01,35.88 v1(6.18,36.05) ; C26.1@6.272,16.6 6.272,17.122 6.55,17.4 v1(7.98,17.4) ; R21.1@6.521,2.475 6.521,3.291 6.63,3.4 v1(7.73,3.4) 7.98,3.15 Q2.2@9.1,3.15 ; v1(7.23,24.24) 7.42,24.05 9.26,24.05 9.35,24.14 C23.1@9.35,24.6 C22.1@10.35,24.6 ; v1(8.3,30.35) 8.3,30.4 8.521,30.179 U7.8@8.521,29.38 ; U8.1@8.343,14.554 8.343,13.447 8.74,13.05 v1(9.58,13.05) ; U5.2@9.1,46.8 9.1,45.999 9.429,45.67 ; v1(9.636,15.68) 9.85,15.894 C25.1@9.85,16.6 ; v1(10.76,17.91) 11.03,17.91 11.25,17.69 C24.1@11.25,16.7 ; CN1.6@11.517,46.142 11.75,45.909 C21.1@11.75,44.8 ; U7.35@11.521,37.88 11.521,38.801 11.7,38.98 v1(11.72,38.96) ; C20.1@13.1,46.05 13.1,45.45 v1(13.11,45.44) ; U7.47@13.521,31.38 14.47,31.38 v1(14.57,31.48)
  Bottom Layer w0.5: 6.517,44.957 CN1.7@6.517,46.142
  other v1: 15.94,0.61 13.55,0.62 17.83,0.65 0.73,0.68 5.097,0.729 5.13,3.92 0.7,4.86 7.24,6.22 5.517,6.34 2.55,7.16 14.46,8.48 12.77,8.5 14.49,9.61 12.54,9.7 0.74,9.71 15.32,10.89 2.63,11.81 17.85,12.06 0.53,12.08 3.92,12.39 5.65,13.51 3.88,14.61 0.61,14.76 17.77,14.78 3.88,16.05 0.59,17.21 17.8,17.27 2.42,17.32 9.347,18.669 0.65,19.82 17.74,19.97 7.92,20.09 10.68,20.16 15.97,22.04 0.67,22.26 15.98,24.87 17.89,27.65 5.59,28.92 4.36,28.96 0.68,29.91 17.82,30 6.58,30.41 0.66,32.31 17.79,32.4 15.02,32.95 12.2,33.67 7.11,33.73 10.04,34.2 8.13,34.31 3.67,34.71 0.7,35.03 17.8,35.09 10.76,36.13 9.19,36.93 5.66,37.08 0.7,37.49 17.86,37.54 5.86,38.49 3.84,38.69 0.7,40 10.36,40.01 3.55,40.52 5.77,40.7 10.55,42.3 12.84,43.14 4.53,43.18 0.7,43.75 0.76,47.07 4.96,47.22 13.53,47.66 16.11,47.67 13.81,49.56 16.05,49.61 4.23,49.63 1.79,49.64
NetC3_2: C3.2 R7.2 SB7.1 | length 30.4
  Top Layer w0.12: v1(5.57,10.23) 5.57,11.18 SB7.1@5.68,11.29 ; v1(6.79,21.05) 6.79,21.295 6.07,22.015 6.07,24.58 6.175,24.685 7.045,24.685 7.31,24.95 7.31,26.038 7.79,26.518 7.79,27.5 7.43,27.86 7.43,29.71 7.66,29.94 7.66,34.03 7.24,34.45 R7.2@7.24,35.27 R7.2@7.26,35.25
  Top Layer w0.2: R7.2@7.26,35.25 C3.2@8.19,35.25
  Bottom Layer w0.12: v1(5.57,10.23) 6.3,10.96 6.3,14.93 5.56,15.67 5.56,19.337 6.073,19.85 6.42,19.85 6.79,20.22 v1(6.79,21.05)
NetC8_2: C8.2 U1.4 | length 1.4
  Top Layer w0.3: C8.2@12.3,28.6 12.35,28.55 U1.4@12.35,27.25
NetC10_2: C10.2 C11.2 D3.2 D4.2 U1.1 U1.3 | length 8.3
  Top Layer w0.12: U1.1@10.45,25.05 10.45,24.34 10.59,24.2 12.24,24.2 12.35,24.31 U1.3@12.35,25.05
  Top Layer w0.5: U1.3@12.35,25.05 13.167,25.05 13.297,25.18 13.81,25.18 v1(13.85,25.22) v1@13.9,25.27 ; C11.2@13.9,24.582 v1@13.9,25.27 ; C10.2@13.926,25.798 13.926,25.296 v1@13.9,25.27
  Bottom Layer w0.5: D4.2@12.8,25.03 13.22,25.03 13.41,25.22 v1(13.85,25.22) 14.04,25.03 D3.2@14.6,25.03
NetC12_2: C12.2 C14.2 SB11.1 U3.4 | length 10.3
  Top Layer w0.5: C12.2@11.92,11.93 C14.2@11.92,11.19 12.32,11.19 12.5,11.01 14.24,11.01 14.45,10.8 U3.4@14.45,10.39
  Bottom Layer w0.5: SB11.1@11.4,5.842 13.47,7.912 13.47,10.06 v1(12.5,11.03)
NetC15_2: C15.2 SB8.1 X1.1 | length 4
  Top Layer w0.2: C15.2@6.471,7.6 6.471,9.121 X1.1@6.55,9.2 6.88,9.53 6.88,11.08 SB8.1@7.1,11.3
NetC16_2: C16.2 SB9.1 X1.2 | length 4
  Top Layer w0.2: SB9.1@8.5,11.3 8.5,10.89 8.72,10.67 8.72,9.53 X1.2@9.05,9.2 9.15,9.1 C16.2@9.15,7.6
NetCN1_4: CN1.4 R2.2 | length 8
  Top Layer w0.12: CN1.4@8.367,46.142 8.367,47.037 9.042,47.712 11.869,47.712 12.72,46.861 12.72,44.83 R2.2@12.8,44.75
NetD1_2: D1.2 R8.1 | length 2.3
  Top Layer w0.3: R8.1@13.017,33.7 13.59,33.7 13.73,33.56 13.73,32.74 13.9,32.57 D1.2@14.4,32.57
NetLD1_2: LD1.2 R17.2 | length 1.8
  Top Layer w0.3: v1(2.65,46.48) 2.655,46.485 LD1.2@2.655,45.363
  Bottom Layer w0.3: v1(2.65,46.48) 2.65,45.9 R17.2@2.7,45.85
NetLD1_3: LD1.3 R18.2 | length 1.8
  Top Layer w0.3: LD1.3@1.155,45.363 1.2,45.408 v1(1.2,46.5)
  Bottom Layer w0.3: R18.2@1.2,45.85 v1(1.2,46.5)
NetLD2_1: LD2.1 R23.1 | length 3.7
  Top Layer w0.3: v1(3.16,1.11) 3.16,2.69 3.582,3.112 LD2.1@4.369,3.112
  Bottom Layer w0.3: R23.1@3.15,1.8 3.16,1.79 v1(3.16,1.11)
NetLD3_1: LD3.1 R20.1 | length 4.2
  Top Layer w0.3: v1(11.88,4.48) 12.16,4.2 13.93,4.2 14.326,3.804 LD3.1@14.326,3.112
  Bottom Layer w0.3: R20.1@11.1,4.5 11.86,4.5 v1(11.88,4.48)
NetLD3_2: LD3.2 Q2.3 | length 3.4
  Top Layer w0.3: v1(13.5,1.57) 14.368,1.57 LD3.2@14.326,1.612
  Bottom Layer w0.3: Q2.3@11.3,2.2 12.87,2.2 v1(13.5,1.57)
NetLD4_1: LD4.1 R3.2 | length 1.3
  Top Layer w0.3: LD4.1@5.1,44.3 5.1,43.64 5.45,43.29 R3.2@5.45,43.1
NetLD4_2: LD4.2 U5.3 | length 3.6
  Top Layer w0.5: LD4.2@6.6,44.3 7.44,44.3 v1(7.46,44.32)
  Bottom Layer w0.5: v1(7.46,44.32) 7.46,45.06 8.15,45.75 U5.3@8.15,46.8
NetQ1_1: Q1.1 R4.2 R5.1 R6.1 | length 3.6
  Top Layer w0.3: Q1.1@11.7,40.452 12.602,40.452 13.2,41.05 14.3,41.05 R6.1@14.3,40.25
NetQ1_2: Q1.2 R1.2 | length 1.5
  Top Layer w0.3: Q1.2@11.7,42.352 R1.2@11.7,43.85
NetQ2_1: Q2.1 R21.2 R22.2 | length 2.9
  Bottom Layer w0.3: R21.2@7.421,2.475 R22.2@7.421,1.25 Q2.1@9.1,1.25
NetR7_1: R7.1 U7.29 | length 2.8
  Top Layer w0.2: R7.1@7.24,36.17 7.24,36.66 7.508,36.928 v1(8.52,36.928)
  Bottom Layer w0.2: v1(8.52,36.928) v1(8.52,36.928) U7.29@8.521,37.88
NetR8_2: R8.2 R9.1 SB1.2 U7.39 | length 5.3
  Top Layer w0.3: v1(11.99,35.67) 13.004,35.67 13.017,35.657 R8.2@13.017,34.6 14.55,34.6 R9.1@14.6,34.65
  Bottom Layer w0.3: v1(11.99,35.67) 12.28,35.38 U7.39@13.521,35.38
NetR12_2: R12.2 U7.3 | length 2.2
  Top Layer w0.3: R12.2@10.643,31.45 10.643,30.807 v1(11.01,30.44)
  Bottom Layer w0.3: v1(11.01,30.44) 11.021,30.429 U7.3@11.021,29.38
NetR13_2: R13.2 U7.2 | length 1.9
  Top Layer w0.3: v1(11.79,30.5) 11.79,31.14 R13.2@11.8,31.15
  Bottom Layer w0.3: U7.2@11.521,29.38 11.521,30.231 v1(11.79,30.5)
